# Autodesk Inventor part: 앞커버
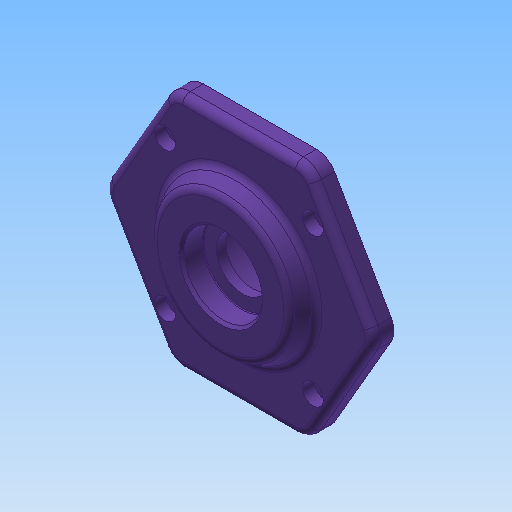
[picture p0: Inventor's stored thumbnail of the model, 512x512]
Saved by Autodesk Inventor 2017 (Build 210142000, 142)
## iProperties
Created: 2013-02
Part Number: 앞커버
Document SubType Name: Modeling
Density: 1 g/cm^3
Material: 일반
Appearance: 보라색
Author: 한국산업디자인학원[gmhk.co.kr]
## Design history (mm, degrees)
sketch "스케치1" dims "d37" = 105
  geometry: L1 (28.559, 41.466)-(50.191, 4); L2 (50.191, -4)-(28.559, -41.466); L3 (21.631, -45.466)-(-21.631, -45.466); L4 (-28.559, -41.466)-(-50.191, -4); L5 (-50.191, 4)-(-28.559, 41.466); L6 (-21.631, 45.466)-(21.631, 45.466); C1 r 30 at (0, 0); A1 r 8 centre (-43.262, 0) between (-50.191, 4) and (-50.191, -4); A2 r 8 centre (-21.631, 37.466) between (-21.631, 45.466) and (-28.559, 41.466); A3 r 8 centre (21.631, 37.466) between (28.559, 41.466) and (21.631, 45.466); A4 r 8 centre (43.262, 0) between (50.191, -4) and (50.191, 4); A5 r 8 centre (21.631, -37.466) between (21.631, -45.466) and (28.559, -41.466); A6 r 8 centre (-21.631, -37.466) between (-28.559, -41.466) and (-21.631, -45.466); 9 further points
  constraints: 12 end point, 12 point on circle, 12 point on line, 12 tangent, 7 centre point, 5 equal radius, 3 coincident, 1 horizontal, 16 other
  dimensions: "d40" = 8 radius of A1; "d41" = 60 diameter of C1
extrude "돌출1" new body sketch "스케치1" distance "d0" = 8; taper "d1" = 0 deg
sketch "스케치2"
  geometry: C1 r 30 at (0, 0); 1 further point
  constraints: 1 centre point, 1 coincident
  dimensions: "d2" = 60 diameter of C1
extrude "돌출2" join sketch "스케치2" distance "d3" = 7; taper "d4" = -30 deg
hole "구멍1" diameter "d7" = 20; stored, may be unused: countersink angle "d11" = 90 deg, drill point angle "d13" = 118 deg; dims "d8" = 6, "d9" = 30, "d10" = 8.3, "d12" = 20, "d52" = 10, "d53" = 10
sketch "스케치3"
  geometry: L1 (-28.284, 28.284)-(0, 0); L2 (0, 0)-(0, 40); L3 (0, 0)-(28.284, 28.284); L4 (0, 0)-(28.284, -28.284); L5 (0, 0)-(-28.284, -28.284); C1 r 1.621 at (28.284, 28.284); C2 r 1.621 at (-28.284, 28.284); C3 r 1.621 at (-28.284, -28.284); C4 r 1.621 at (28.284, -28.284); C5 r 10 at (0, 0) reference; A1 r 40 centre (0, 0) between (28.284, 28.284) and (-28.284, 28.284)
  constraints: 10 end point, 5 centre point, 3 perpendicular, 3 point on circle, 1 coincident, 1 vertical
  dimensions: "d48" = 80 diameter of A1; "d50" = 45 deg angle of L2 L1
hole "구멍2" sketch "스케치3" at (28.284, 28.284), (28.284, -28.284), (-28.284, -28.284), (-28.284, 28.284) diameter "d14" = 4.5; stored, may be unused: countersink angle "d18" = 90 deg, drill point angle "d20" = 118 deg; dims "d15" = 6, "d16" = 8, "d17" = 4.4, "d19" = 20
extrude "돌출3" join sketch "스케치1" distance "d21" = 12; taper "d22" = 0 deg
hole "구멍3" diameter "d25" = 30; stored, may be unused: countersink angle "d29" = 90 deg, drill point angle "d31" = 0 deg; dims "d26" = 6, "d27" = 40, "d28" = 12, "d30" = 15, "d42" = 10, "d43" = 10
fillet "모깎기1" dims "d32" = 3, "d33" = 0.3
chamfer "모따기1" distance "d34" = 1; stored, may be unused: second distance "d35" = 2, angle "d36" = 45 deg
chamfer "모따기2" distance "d44" = 1; stored, may be unused: second distance "d45" = 2, angle "d46" = 45 deg
fillet "모깎기2" dims "d47" = 3
fillet "모깎기3" dims "d54" = 0.6
node "솔리드1"
